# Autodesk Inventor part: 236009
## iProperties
Created: 2006-08
Part Number: 236009
Material: St vz
Description: Scheibe
Vendor: Autodesk Inc.
Document SubType Name: Modeling
Standard: DIN 125
Designer: I.Baliuc
Standards Organization: DIN
Language: de-DE
Size Designation: A 5.3
Categories: <MemberInstance Version="R10.0.0"><Categories><Category DisplayName="Schrauben" InternalName="e4da775c-781d-43d5-af7c-5136215cf5a6" Mnemonic="FSTN"><Category Di
Density: 7.85 g/cm^3
Abmessung: A 5
Author: T.Messerschmitt
Comments: DIN 125 - A 5.3
Revision Number: 236009
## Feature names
1. Körper [Extrusion]
